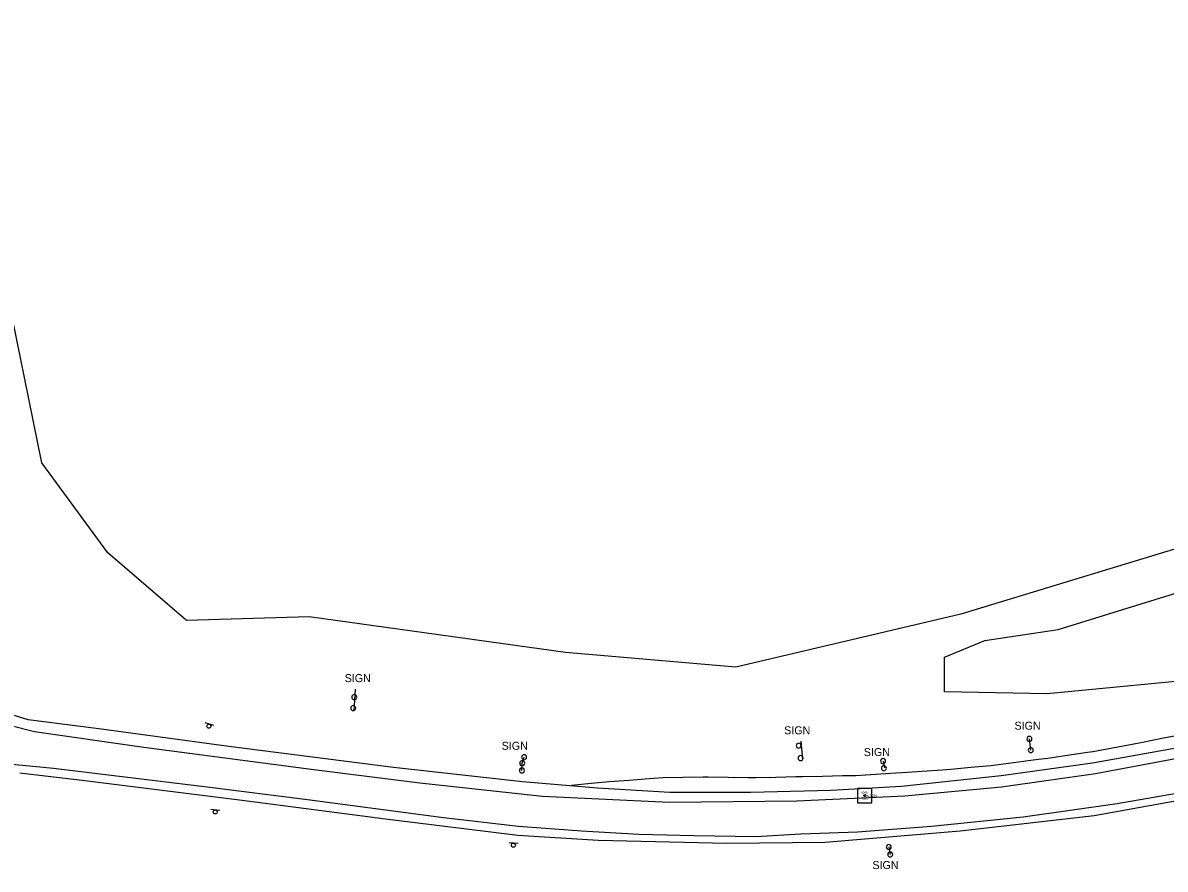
# Model space of a CAD drawing. Extents: x 1901471 to 1963503, y 756461 to 799997.
# Drawn here: x 1912024 to 1912595, y 762367 to 762790 of the extents above; entities that cross this region are included whole.
import ezdxf

# ---------------------------------------------------------------- set-up
doc = ezdxf.new("R2010")
doc.units = 0
for name, color, linetype in [('Default', 7, 'Continuous'), ('RD_DTM_BkLn1', 7, 'Continuous'), ('RD_EX_Bldg', 7, 'Continuous'), ('RD_EX_BldgApp', 7, 'Continuous'), ('RD_EX_Road', 7, 'Continuous'), ('RD_EX_Road_txCode', 7, 'Continuous'), ('RD_EX_VEG', 7, 'Continuous'), ('RD_HC_Survey', 7, 'Continuous'), ('RD_HC_txCode', 7, 'Continuous'), ('RD_SMD_Locator', 7, 'Continuous')]:
    doc.layers.add(name, color=color, linetype=linetype)

# ---------------------------------------------------------------- blocks, each defined once
blk = doc.blocks.new('SIGNPOST')
at = {"layer": 'Default'}
for start, end in [(90, 270), (270, 90)]:
    blk.add_arc((0, 0), 0.127, start, end, dxfattribs=at)
blk = doc.blocks.new('SIGN')
at = {"layer": 'RD_EX_BldgApp'}
blk.add_line((-4.5, -2), (4.5, -2), dxfattribs=at)
blk.add_circle((0, 0), 2, dxfattribs=at)

msp = doc.modelspace()

# ---------------------------------------------------------------- linework, layer by layer
at = {"layer": 'RD_DTM_BkLn1'}
msp.add_lwpolyline([(1912298, 762409.12), (1912307.95, 762410.1), (1912316.96, 762410.98), (1912326.93, 762411.69), (1912336.9, 762412.41), (1912343.81, 762412.9), (1912353.81, 762413.08), (1912363.8, 762413.25), (1912366.44, 762413.29), (1912376.44, 762413.13), (1912386.43, 762412.98), (1912390.2, 762412.92), (1912400.19, 762413.17), (1912410.19, 762413.43), (1912413.46, 762413.52), (1912423.45, 762413.7), (1912433.45, 762413.89), (1912440.21, 762414.02), (1912450.19, 762414.64), (1912460.16, 762415.26), (1912463.29, 762415.45), (1912473.26, 762416.14), (1912483.24, 762416.82), (1912487.69, 762417.12), (1912497.64, 762418.07), (1912507.6, 762419.02), (1912511.51, 762419.39), (1912521.42, 762420.72), (1912531.33, 762422.05), (1912536.11, 762422.69), (1912546, 762424.14), (1912555.89, 762425.59), (1912558.61, 762425.99), (1912568.44, 762427.83), (1912578.27, 762429.66), (1912583.34, 762430.61), (1912593.14, 762432.55), (1912602.95, 762434.5)], dxfattribs=at)
at = {"layer": 'RD_EX_Bldg'}
for points in [[(1912189.52, 762446.24), (1912190.21, 762457.09)], [(1912413.66, 762422), (1912412.84, 762431.06)], [(1912527.59, 762426.65), (1912526.9, 762432.23)], [(1912273.3, 762416.51), (1912273.43, 762420.08), (1912274.4, 762423.1)], [(1912454.59, 762417.88), (1912454.04, 762421.18)], [(1912456.65, 762378.27), (1912457.35, 762374.55)]]:
    msp.add_lwpolyline(points, dxfattribs=at)
at = {"layer": 'RD_EX_Road'}
for points in [[(1913368.02, 762794.1), (1913299.68, 762754.35), (1913199.62, 762696.79), (1913121.12, 762651.36), (1913047.44, 762608.97), (1912966.22, 762562.71), (1912911.58, 762532.67), (1912876.42, 762515.09), (1912834.97, 762495.83), (1912784.1, 762475), (1912738.89, 762458.67), (1912692, 762443.81), (1912629.2, 762427.8), (1912559.91, 762414.82), (1912513.02, 762408.12), (1912464.67, 762403.62), (1912410.66, 762401.11), (1912346.81, 762400.48), (1912283.6, 762403.52), (1912222.26, 762410.22), (1912168.05, 762416.91), (1912084.31, 762427.9), (1912029.68, 762435.75), (1912007.91, 762441.2)], [(1912604.92, 762428.53), (1912558.44, 762420.05), (1912512.81, 762413.77), (1912462.99, 762408.54), (1912427.61, 762406.45), (1912387.63, 762405.51), (1912347.23, 762405.51), (1912311.02, 762407.6), (1912273.55, 762410.74), (1912209.07, 762417.96), (1912126.81, 762428.43), (1912061.92, 762437.22), (1912026.54, 762441.82), (1912009.16, 762447.16)], [(1912523.76, 762393.22), (1912478.02, 762388.56), (1912441.06, 762385.72), (1912412.64, 762384.69), (1912390.15, 762383.4), (1912359.4, 762383.78), (1912331.75, 762384.56), (1912303.06, 762386.11), (1912271.53, 762388.44), (1912234.06, 762392.83), (1912166.09, 762401.74), (1912115.96, 762408.21), (1912039.2, 762417.51), (1912009.74, 762420.35)], [(1912622.92, 762405.3), (1912559.28, 762393.78), (1912492.3, 762386.14), (1912424.89, 762380.49), (1912375.7, 762379.97), (1912311.44, 762381.43), (1912271.25, 762383.94), (1912205.1, 762392.21), (1912133.51, 762401.42), (1912054.8, 762411.37), (1912022.35, 762415.13)], [(1912615.8, 762407.7), (1912570.8, 762399.75), (1912523.76, 762393.22)]]:
    msp.add_lwpolyline(points, dxfattribs=at)
at = {"layer": 'RD_EX_VEG'}
msp.add_lwpolyline([(1913294.28, 762873.41), (1913149.42, 762779.14), (1913146.98, 762760.66), (1913125.59, 762752.4), (1913103.22, 762749.48), (1913003.3, 762696.81), (1912968.52, 762680.43), (1912962.68, 762666.81), (1912940.8, 762652.71), (1912921.84, 762658.54), (1912836.76, 762616.28), (1912759.9, 762574.19), (1912682.12, 762547.66), (1912607.09, 762529.36), (1912492.71, 762494.58), (1912380.16, 762468.05), (1912295.07, 762475.37), (1912166.96, 762493.21), (1912105.65, 762491.38), (1912066.31, 762525.24), (1912033.37, 762570.07), (1911994.94, 762758.57), (1911982.44, 762886.63)], dxfattribs=at)
msp.add_lwpolyline([(1912541.21, 762486.81), (1912656.5, 762522.49), (1912741.6, 762547.2), (1912808.4, 762576.48), (1912842.25, 762587.46), (1912881.6, 762570.07), (1912870.62, 762540.79), (1912789.18, 762507.85), (1912694.93, 762482.23), (1912622.65, 762463.02), (1912535.72, 762454.78), (1912484.48, 762455.7), (1912484.48, 762473.08), (1912504.61, 762481.32)], close=True, dxfattribs=at)
at = {"layer": 'RD_HC_Survey'}
msp.add_lwpolyline([(1912448.16, 762407.44), (1912441.08, 762407.44), (1912441.08, 762400.37), (1912448.16, 762400.37)], close=True, dxfattribs=at)
msp.add_circle((1912444.62, 762403.91), 0.5, dxfattribs=at)
at = {"layer": 'RD_SMD_Locator'}
msp.add_circle((1912444.62, 762403.91), 0.001, dxfattribs=at)

# ---------------------------------------------------------------- block references
at = {"layer": 'RD_EX_Bldg', "xscale": 9.84251968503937, "yscale": 9.84251968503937}
for p in [(1912189.52, 762453.11), (1912188.97, 762447.61), (1912526.9, 762432.23), (1912411.6, 762428.87), (1912527.59, 762426.65), (1912273.43, 762420.08), (1912274.4, 762423.1), (1912412.56, 762422.69), (1912453.76, 762421.18), (1912273.3, 762416.51), (1912454.18, 762417.61), (1912456.65, 762378.27), (1912457.35, 762374.55)]:
    msp.add_blockref('SIGNPOST', p, dxfattribs=at)
at = {"layer": 'RD_EX_Bldg'}
for p, xscale, yscale, rotation in [((1912116.87, 762438.62), 0.5039370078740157, 0.5039370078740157, 162.255328), ((1912120.02, 762395.77), 0.5039370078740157, 0.5039370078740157, 174.289407), ((1912269.04, 762379.15), 0.5039370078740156, 0.5039370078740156, 175.710847)]:
    msp.add_blockref('SIGN', p, dxfattribs=dict(at, xscale=xscale, yscale=yscale, rotation=rotation))

# ---------------------------------------------------------------- texts
at = {"layer": 'RD_EX_Road'}
for p in [(1912184.71, 762460.61), (1912404.35, 762434.55), (1912519.46, 762436.84), (1912263.17, 762426.82), (1912444.15, 762423.67), (1912448.44, 762367.26)]:
    msp.add_text('SIGN', height=4, dxfattribs=at).set_placement(p)
at = {"layer": 'RD_EX_Road_txCode'}
msp.add_text('442.260', height=1, dxfattribs=at).set_placement((1912445.62, 762403.41))
at = {"layer": 'RD_HC_txCode'}
for s, p in [('9000', (1912442.87, 762404.91)), ('MSC', (1912443.31, 762401.91))]:
    msp.add_text(s, height=1, dxfattribs=at).set_placement(p)

doc.saveas('drawing.dxf')
